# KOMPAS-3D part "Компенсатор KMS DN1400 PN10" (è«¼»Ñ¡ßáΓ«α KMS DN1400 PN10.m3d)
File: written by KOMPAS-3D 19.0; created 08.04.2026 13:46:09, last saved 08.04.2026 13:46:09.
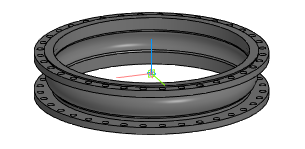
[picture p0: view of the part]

Document properties: Автор: Энергия; Полное имя файла: Z:\3.Личные\kachalov\3d для проектировщиков\7.1 Компенсатор\stp_Компенсатор KSM\Компенсатор KMS DN1400 PN10.m3d

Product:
- Part/product: Компенсатор KMS DN1400 PN10

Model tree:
1. Операция без истории:1  (labels: Компенсатор KMS DN1400 PN10)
